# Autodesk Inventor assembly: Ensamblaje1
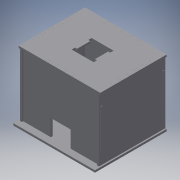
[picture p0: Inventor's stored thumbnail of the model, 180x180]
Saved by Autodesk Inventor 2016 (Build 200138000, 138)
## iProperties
Created: 2016-06
Part Number: Ensamblaje1
Material: Genérico
Document SubType Name: Assembly
Designer: adm
Author: adm
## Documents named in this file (6)
- C:\Users\adm\Desktop\recepcion 1\Ensamblaje1.iam
- C:\Users\adm\Desktop\recepcion 1\base.ipt
- C:\Users\adm\Desktop\recepcion 1\Lateral(puerta).ipt
- C:\Users\adm\Desktop\recepcion 1\Lateral 2.ipt
- C:\Users\adm\Desktop\recepcion 1\Lateral0.ipt
- C:\Users\adm\Desktop\recepcion 1\tapa.ipt
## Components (6 placed, 5 different names)
1. base:1 — Coincidencia:1, Coincidencia:2, Coincidencia:3, Coincidencia:4, Coincidencia:5, Coincidencia:6, Nivelación:1, Coincidencia:7, Nivelación:2, Coincidencia:11
2. Lateral(puerta):1 — Coincidencia:1, Coincidencia:2, Coincidencia:3, Coincidencia:8, Coincidencia:14
3. Lateral 2:1 — Coincidencia:4, Coincidencia:5, Coincidencia:6, Coincidencia:9, Coincidencia:10
4. Lateral0:1 — Nivelación:1, Coincidencia:7, Coincidencia:8
5. Lateral0:3 — Coincidencia:9, Coincidencia:10, Nivelación:2, Coincidencia:11, Coincidencia:12, Coincidencia:13
6. tapa:1 — Coincidencia:12, Coincidencia:13, Coincidencia:14
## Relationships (16: Mate 14, Flush 2)
- Coincidencia:1 [Mate]: base:1 ↔ Lateral(puerta):1
- Coincidencia:2 [Mate]: base:1 ↔ Lateral(puerta):1
- Coincidencia:3 [Mate]: base:1 ↔ Lateral(puerta):1
- Coincidencia:4 [Mate]: base:1 ↔ Lateral 2:1
- Coincidencia:5 [Mate]: base:1 ↔ Lateral 2:1
- Coincidencia:6 [Mate]: base:1 ↔ Lateral 2:1
- Nivelación:1 [Flush]: base:1 ↔ Lateral0:1
- Coincidencia:7 [Mate]: base:1 ↔ Lateral0:1
- Coincidencia:8 [Mate]: Lateral(puerta):1 ↔ Lateral0:1
- Coincidencia:9 [Mate]: Lateral 2:1 ↔ Lateral0:3
- Coincidencia:10 [Mate]: Lateral 2:1 ↔ Lateral0:3
- Nivelación:2 [Flush]: base:1 ↔ Lateral0:3
- Coincidencia:11 [Mate]: base:1 ↔ Lateral0:3
- Coincidencia:12 [Mate]: Lateral0:3 ↔ tapa:1
- Coincidencia:13 [Mate]: Lateral0:3 ↔ tapa:1
- Coincidencia:14 [Mate]: Lateral(puerta):1 ↔ tapa:1
